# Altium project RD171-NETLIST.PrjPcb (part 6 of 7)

## Sheet 7.SchDoc
size 420 x 297 mm
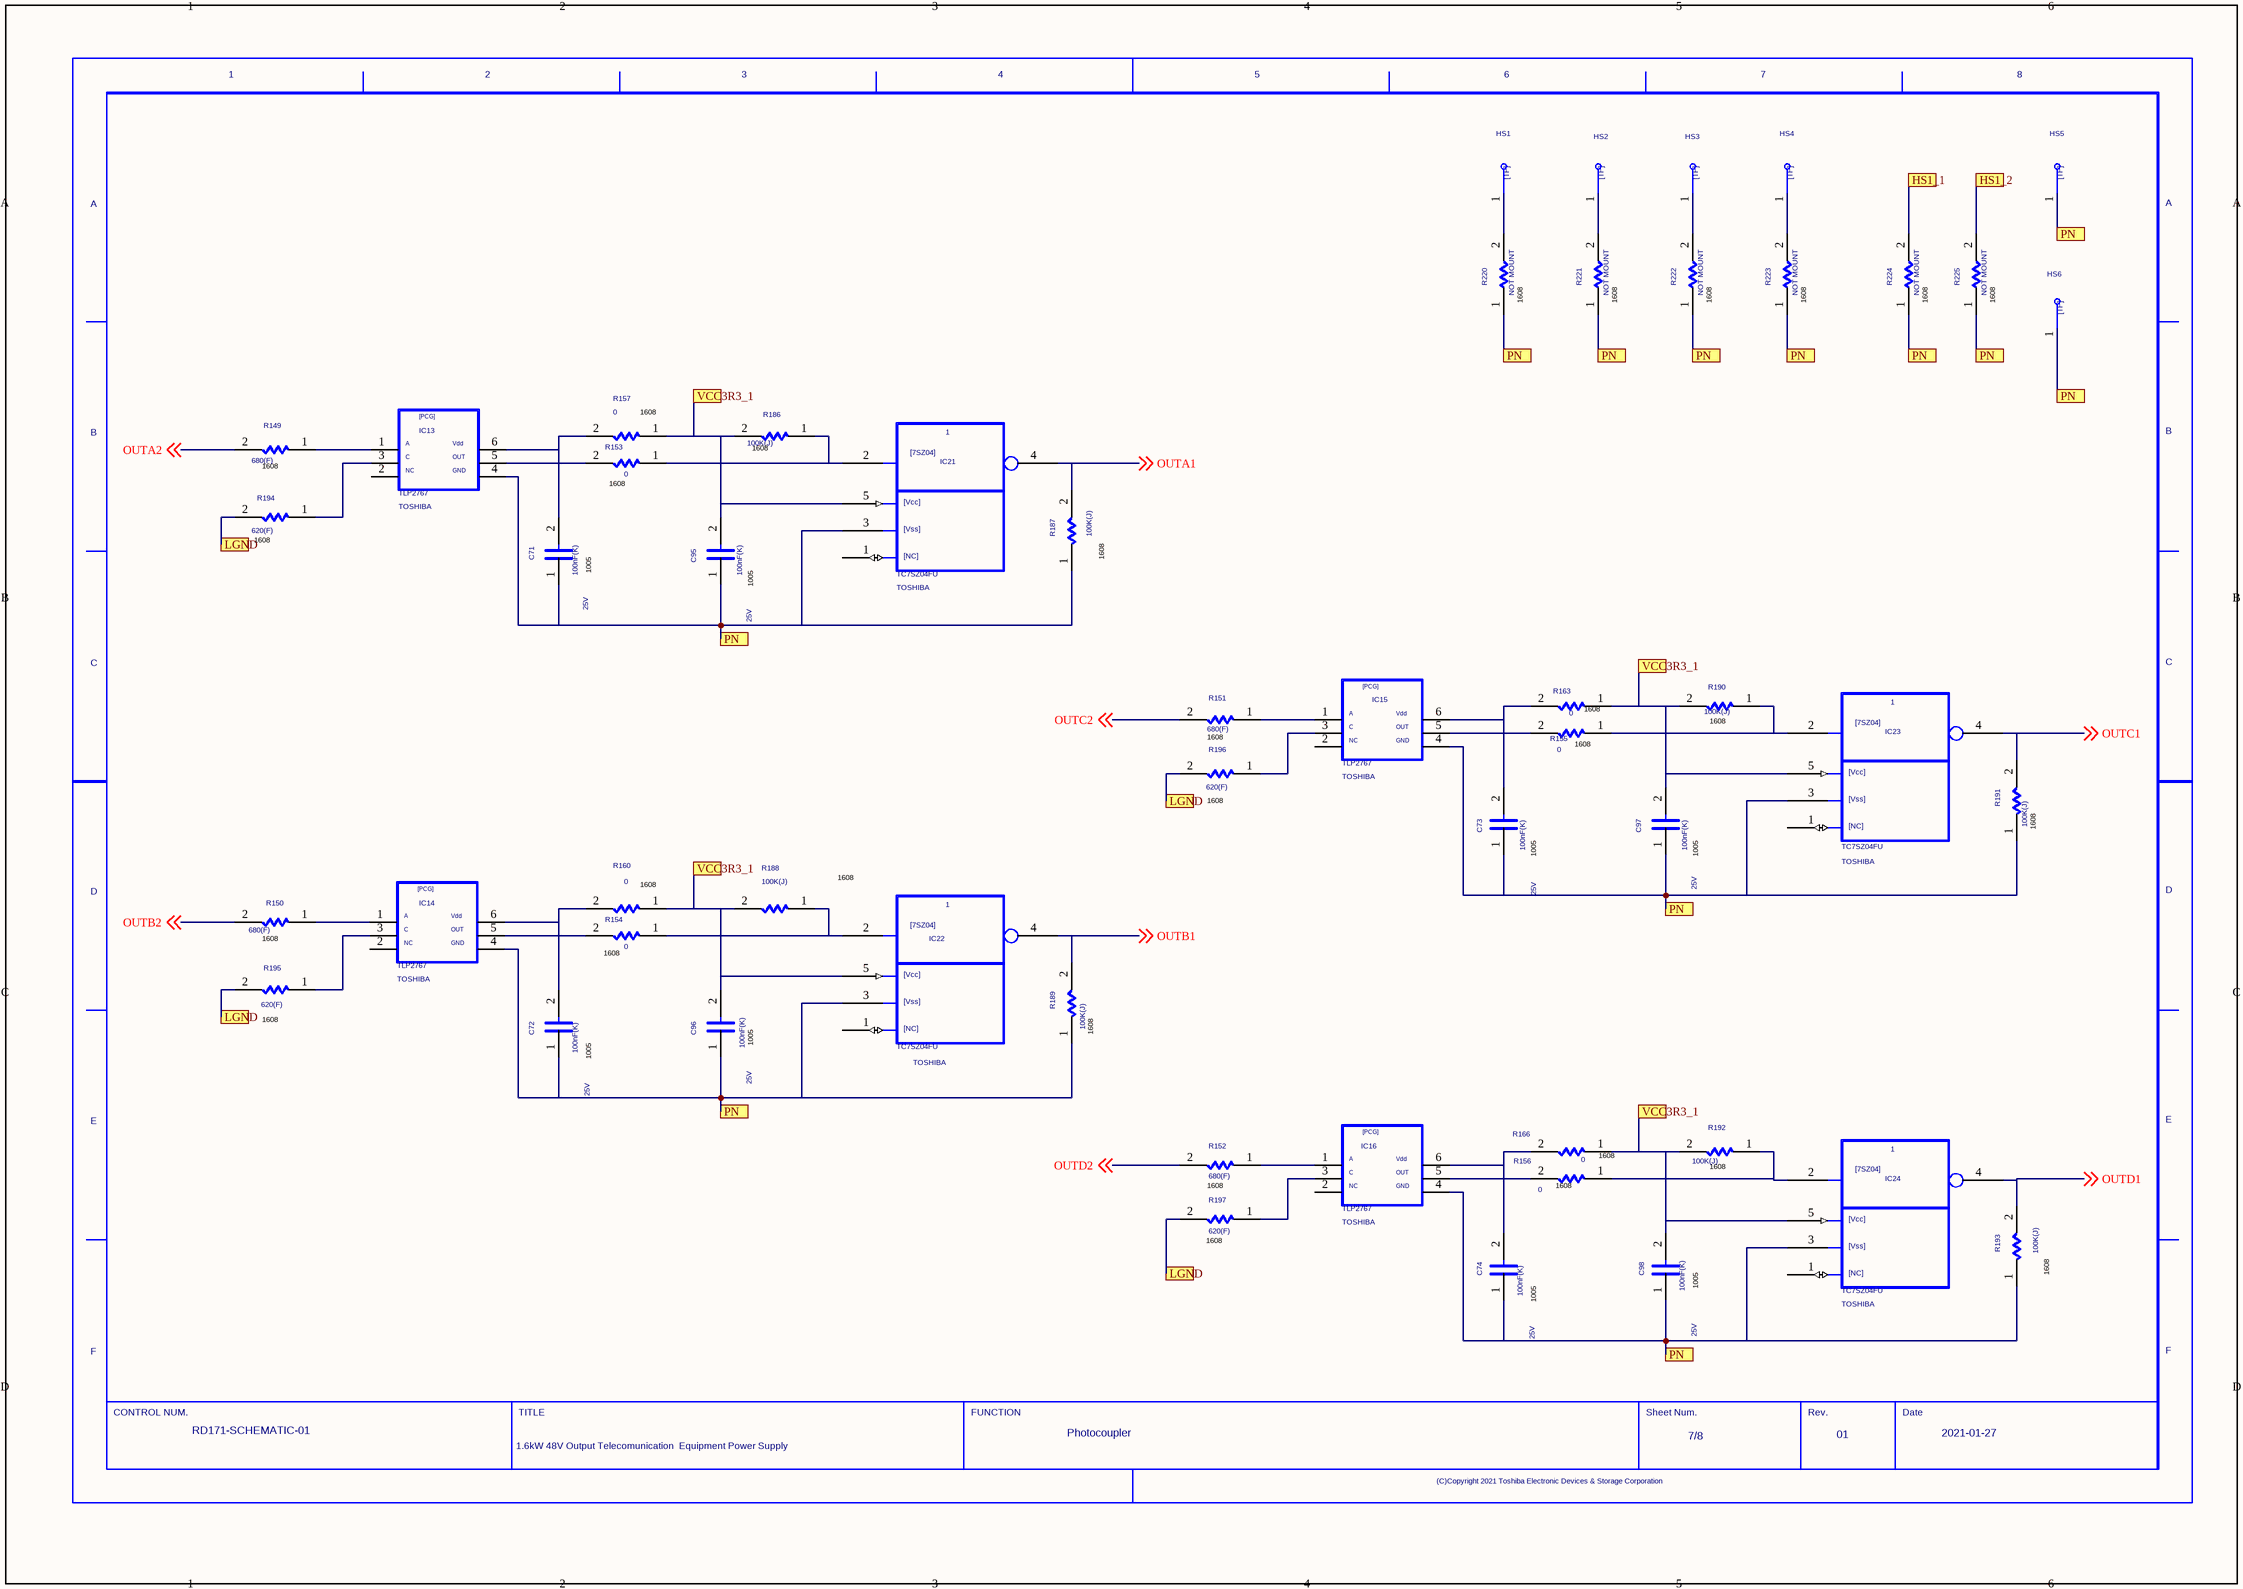
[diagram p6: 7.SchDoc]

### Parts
(Parts that share a designator on the sheet are numbered #1, #2 ... from top to bottom, then left to right.)
C71  VAL2: 25V  VAL1: 100nF(K)  (hidden comment: 100nF)
C72  VAL2: 25V  VAL1: 100nF(K)  (hidden comment: 100nF)
C73  VAL2: 25V  VAL1: 100nF(K)  (hidden comment: 100nF)
C74  VAL2: 25V  VAL1: 100nF(K)  (hidden comment: 100nF)
C95  VAL2: 25V  VAL1: 100nF(K)  (hidden comment: 100nF)
C96  VAL2: 25V  VAL1: 100nF(K)  (hidden comment: 100nF)
C97  VAL2: 25V  VAL1: 100nF(K)  (hidden comment: 100nF)
C98  VAL2: 25V  VAL1: 100nF(K)  (hidden comment: 100nF)
HS1  HS1  [HOLE2.8]  (value not drawn)
HS2  HS2  [HOLE2.8]  (value not drawn)
HS3  HS3  [HOLE2.8]  (value not drawn)
HS4  HS4  [HOLE2.8]  (value not drawn)
HS5  HS5  [HOLE2.0]  (value not drawn)
HS6  HS5  [HOLE2.0]  (value not drawn)
IC13  USERCOMPTEXT3: TOSHIBA  [TLP2767]  (hidden comment: IC13)
IC14  USERCOMPTEXT3: TOSHIBA  [TLP2767]  (hidden comment: IC14)
IC15  USERCOMPTEXT3: TOSHIBA  [TLP2767]  (hidden comment: IC15)
IC16  USERCOMPTEXT3: TOSHIBA  [TLP2767]  (hidden comment: IC16)
IC21  USERCOMPTEXT3: TOSHIBA  [TC7SZ04FU]  (hidden comment: IC21)
IC22  USERCOMPTEXT3: TOSHIBA  [TC7SZ04FU]  (hidden comment: IC22)
IC23  USERCOMPTEXT3: TOSHIBA  [TC7SZ04FU]  (hidden comment: IC23)
IC24  USERCOMPTEXT3: TOSHIBA  [TC7SZ04FU]  (hidden comment: IC24)
R149  VAL1: 680(F)  (hidden comment: 680)
R150  VAL1: 680(F)  (hidden comment: 680)
R151  VAL1: 680(F)  (hidden comment: 680)
R152  VAL1: 680(F)  (hidden comment: 680)
R153  0
R154  0
R155  0
R156  0
R157  0
R160  0
R163  0
R166  0
R186  VAL1: 100K(J)  (hidden comment: 100k)
R187  VAL1: 100K(J)  (hidden comment: 100k)
R188  VAL1: 100K(J)  (hidden comment: 100k)
R189  VAL1: 100K(J)  (hidden comment: 100k)
R190  VAL1: 100K(J)  (hidden comment: 100k)
R191  VAL1: 100K(J)  (hidden comment: 100k)
R192  VAL1: 100K(J)  (hidden comment: 100k)
R193  VAL1: 100K(J)  (hidden comment: 100k)
R194  VAL1: 620(F)  (hidden comment: 620)
R195  VAL1: 620(F)  (hidden comment: 620)
R196  VAL1: 620(F)  (hidden comment: 620)
R197  VAL1: 620(F)  (hidden comment: 620)
R220  NOTMOUNT: NOT MOUNT  (hidden comment: 0)
R221  NOTMOUNT: NOT MOUNT  (hidden comment: 0)
R222  NOTMOUNT: NOT MOUNT  (hidden comment: 0)
R223  NOTMOUNT: NOT MOUNT  (hidden comment: 0)
R224  NOTMOUNT: NOT MOUNT  (hidden comment: 0)
R225  NOTMOUNT: NOT MOUNT  (hidden comment: 0)
U?#7  DATE: 2021-01-27  REVISION: 01  SHEETNUMBER: 7/8  FUNCTION: Photocoupler  TITLE: 1.6kW 48V Output Telecomunication / Equipment Power Supply  DRAWINGNUMBER: RD171-SCHEMATIC-01  (hidden comment: WAKU_DEF100)

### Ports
HS1_1, HS1_2, LGND, PN, VCC3R3_1

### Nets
LGND: R194.2 R195.2 R196.2 R197.2 ; port LGND
OUTA1: IC21.4 R187.2 ; off-sheet OUTA1
OUTA2: R149.2 ; off-sheet OUTA2
OUTB1: IC22.4 R189.2 ; off-sheet OUTB1
OUTB2: R150.2 ; off-sheet OUTB2
OUTC1: IC23.4 R191.2 ; off-sheet OUTC1
OUTC2: R151.2 ; off-sheet OUTC2
OUTD1: IC24.4 R193.2 ; off-sheet OUTD1
OUTD2: R152.2 ; off-sheet OUTD2
SIG228: IC13.5 R153.2
SIG229: C71.2 IC13.6 R157.2
SIG230: IC13.1 R149.1
SIG231: C72.2 IC14.6 R160.2
SIG234: IC14.5 R154.2
SIG236: IC14.1 R150.1
SIG237: C73.2 IC15.6 R163.2
SIG242: IC15.5 R155.2
SIG243: IC16.1 R152.1
SIG245: IC16.5 R156.2
SIG246: C74.2 IC16.6 R166.2
SIG247: IC15.1 R151.1
SIGN284: IC13.3 R194.1
SIGN287: IC14.3 R195.1
SIGN289: IC16.3 R197.1
SIGN291: IC15.3 R196.1
SIGN304: IC21.2 R153.1 R186.1
SIGN305: IC22.2 R154.1 R188.1
SIGN314: IC23.2 R155.1 R190.1
SIGN315: IC24.2 R156.1 R192.1
SIGN366: HS1.1 R220.2
SIGN369: HS2.1 R221.2
SIGN371: HS3.1 R222.2
SIGN373: HS4.1 R223.2
NetC1_1: C71.1 C72.1 C73.1 C74.1 C95.1 C96.1 C97.1 C98.1 HS5.1 HS6.1 IC13.4 IC14.4 IC15.4 IC16.4 IC21.3 IC22.3 IC23.3 IC24.3 R187.1 R189.1 R191.1 R193.1 R220.1 R221.1 R222.1 R223.1 R224.1 R225.1 ; port PN
NetC95_2: C95.2 C96.2 C97.2 C98.2 IC21.5 IC22.5 IC23.5 IC24.5 R157.1 R160.1 R163.1 R166.1 R186.2 R188.2 R190.2 R192.2 ; port VCC3R3_1
NetR224_2: R224.2 ; port HS1_1
NetR225_2: R225.2 ; port HS1_2

Not connected (* = marked no-connect by the designer): IC13 2; IC14 2; IC15 2; IC16 2; IC21 1; IC22 1; IC23 1; IC24 1

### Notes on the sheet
- (near R220) 1608
- (near R221) 1608
- (near R222) 1608
- (near R223) 1608
- (near R224) 1608
- (near R225) 1608
- (near R157) 1608
- (near R186) 1608
- (near R149) 1608
- (near R153) 1608
- (near R194) 1608
- (near C71) 1005
- (near C95) 1005
- (near R187) 1608
- (near R163) 1608
- (near R190) 1608
- (near R196) 1608
- (near R151) 1608
- (near R155) 1608
- (near C73) 1005
- (near C97) 1005
- (near R191) 1608
- (near R160) 1608
- 1608
- (near R150) 1608
- (near R154) 1608
- (near R195) 1608
- (near C72) 1005
- (near C96) 1005
- (near R189) 1608
- (near R156) 1608
- (near R192) 1608
- (near R197) 1608
- (near R193) 1608
- (near C74) 1005
- (near C98) 1005

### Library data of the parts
C71 = C: PARTNAME: Chip1005_GS_2; ORIGINALSYMBOLORIGIN: (0,0); TIME: 16:40:04; UPDATEUSER: t5459927; SAVECOUNT: 1; QUADMODEL: CON_100N; FUNCTION: C_C.Normal_package; NOMINALCAPACITA: 100n; RATEDVOLTAGE: 25; CDMASTERCADCELG: KC0005; MAKER: TDK; SIZECODESMD: 1005; OUMEMAKER: MRT 村田製作所; ADSCNVFLAG: ON; ADSCOMPONENTNAME: C_1005; COMP: PRT_52; ADSMODELNAME: s_GRM155R71E104KE14D; FNLEADFREETHET1GT2GMCTH1: N_N_N; VAL3: C1005X7R1E104K050BB; CAPACITANCETOLE: K; OUMECLASSIFICATION: セラミックコンデンサ; OUMEMAKERKATAMEI: GRM155R71E104KE14D; INSTANCENAME: INS10182
C72 = C: PARTNAME: Chip1005_GS_2; ORIGINALSYMBOLORIGIN: (0,0); TIME: 16:40:04; UPDATEUSER: t5459927; SAVECOUNT: 1; QUADMODEL: CON_100N; FUNCTION: C_C.Normal_package; NOMINALCAPACITA: 100n; RATEDVOLTAGE: 25; CDMASTERCADCELG: KC0005; MAKER: TDK; SIZECODESMD: 1005; OUMEMAKER: MRT 村田製作所; ADSCNVFLAG: ON; ADSCOMPONENTNAME: C_1005; COMP: PRT_52; ADSMODELNAME: s_GRM155R71E104KE14D; FNLEADFREETHET1GT2GMCTH1: N_N_N; VAL3: C1005X7R1E104K050BB; CAPACITANCETOLE: K; OUMECLASSIFICATION: セラミックコンデンサ; OUMEMAKERKATAMEI: GRM155R71E104KE14D; INSTANCENAME: INS10192
C73 = C: PARTNAME: Chip1005_GS_2; ORIGINALSYMBOLORIGIN: (0,0); TIME: 16:40:04; UPDATEUSER: t5459927; SAVECOUNT: 1; QUADMODEL: CON_100N; FUNCTION: C_C.Normal_package; NOMINALCAPACITA: 100n; RATEDVOLTAGE: 25; CDMASTERCADCELG: KC0005; MAKER: TDK; SIZECODESMD: 1005; OUMEMAKER: MRT 村田製作所; ADSCNVFLAG: ON; ADSCOMPONENTNAME: C_1005; COMP: PRT_52; ADSMODELNAME: s_GRM155R71E104KE14D; FNLEADFREETHET1GT2GMCTH1: N_N_N; VAL3: C1005X7R1E104K050BB; CAPACITANCETOLE: K; OUMECLASSIFICATION: セラミックコンデンサ; OUMEMAKERKATAMEI: GRM155R71E104KE14D; INSTANCENAME: INS10222
C74 = C: PARTNAME: Chip1005_GS_2; ORIGINALSYMBOLORIGIN: (0,0); TIME: 16:40:04; UPDATEUSER: t5459927; SAVECOUNT: 1; QUADMODEL: CON_100N; FUNCTION: C_C.Normal_package; NOMINALCAPACITA: 100n; RATEDVOLTAGE: 25; CDMASTERCADCELG: KC0005; MAKER: TDK; SIZECODESMD: 1005; OUMEMAKER: MRT 村田製作所; ADSCNVFLAG: ON; ADSCOMPONENTNAME: C_1005; COMP: PRT_52; ADSMODELNAME: s_GRM155R71E104KE14D; FNLEADFREETHET1GT2GMCTH1: N_N_N; VAL3: C1005X7R1E104K050BB; CAPACITANCETOLE: K; OUMECLASSIFICATION: セラミックコンデンサ; OUMEMAKERKATAMEI: GRM155R71E104KE14D; INSTANCENAME: INS10252
C95 = C: PARTNAME: Chip1005_GS_2; ORIGINALSYMBOLORIGIN: (0,0); TIME: 16:40:04; UPDATEUSER: t5459927; SAVECOUNT: 1; COMPONENTNAME: C_C.Normal_package; SIZECODESMD: 1005; RATEDVOLTAGE: 25; ADSMODELNAME: s_GRM155R71E104KE14D; CAPACITANCETOLE: K; NOMINALCAPACITA: 100n; VAL3: C1005X7R1E104K050BB; MAKER: TDK; COMP: PRT_52; ADSCOMPONENTNAME: C_1005; INSTANCENAME: INS10380
C96 = C: PARTNAME: Chip1005_GS_2; ORIGINALSYMBOLORIGIN: (0,0); TIME: 16:40:04; UPDATEUSER: t5459927; SAVECOUNT: 1; COMPONENTNAME: C_C.Normal_package; SIZECODESMD: 1005; RATEDVOLTAGE: 25; ADSMODELNAME: s_GRM155R71E104KE14D; CAPACITANCETOLE: K; NOMINALCAPACITA: 100n; VAL3: C1005X7R1E104K050BB; MAKER: TDK; COMP: PRT_52; ADSCOMPONENTNAME: C_1005; INSTANCENAME: INS10448
C97 = C: PARTNAME: Chip1005_GS_2; ORIGINALSYMBOLORIGIN: (0,0); TIME: 16:40:04; UPDATEUSER: t5459927; SAVECOUNT: 1; COMPONENTNAME: C_C.Normal_package; SIZECODESMD: 1005; RATEDVOLTAGE: 25; ADSMODELNAME: s_GRM155R71E104KE14D; CAPACITANCETOLE: K; NOMINALCAPACITA: 100n; VAL3: C1005X7R1E104K050BB; MAKER: TDK; COMP: PRT_52; ADSCOMPONENTNAME: C_1005; INSTANCENAME: INS10544
C98 = C: PARTNAME: Chip1005_GS_2; ORIGINALSYMBOLORIGIN: (0,0); TIME: 16:40:04; UPDATEUSER: t5459927; SAVECOUNT: 1; COMPONENTNAME: C_C.Normal_package; SIZECODESMD: 1005; RATEDVOLTAGE: 25; ADSMODELNAME: s_GRM155R71E104KE14D; CAPACITANCETOLE: K; NOMINALCAPACITA: 100n; VAL3: C1005X7R1E104K050BB; MAKER: TDK; COMP: PRT_52; ADSCOMPONENTNAME: C_1005; INSTANCENAME: INS10534
HS1 = TP: PARTNAME: TP_I_TH2.8_TBLC3.8_ILC0_RC3.9_GS; UPDATEUSER: t5459927; UPDATETIME: 16:40:05; SAVECOUNT: 1; SAVEAREA0: -242,-92,12810,7836; ORIGINALSYMBOLORIGIN: (0,0); COMPONENTNAME: TP_TP.Normal_package; COMP: PRT_39; CHIPSIZE: Through Hole; INSTANCENAME: INS10726
HS2 = TP: PARTNAME: TP_I_TH2.8_TBLC3.8_ILC0_RC3.9_GS; UPDATEUSER: t5459927; UPDATETIME: 16:40:05; SAVECOUNT: 1; SAVEAREA0: -242,-92,12810,7836; ORIGINALSYMBOLORIGIN: (0,0); COMPONENTNAME: TP_TP.Normal_package; COMP: PRT_39; CHIPSIZE: Through Hole; INSTANCENAME: INS10734
HS3 = TP: PARTNAME: TP_I_TH2.8_TBLC3.8_ILC0_RC3.9_GS; UPDATEUSER: t5459927; UPDATETIME: 16:40:05; SAVECOUNT: 1; SAVEAREA0: -242,-92,12810,7836; ORIGINALSYMBOLORIGIN: (0,0); COMPONENTNAME: TP_TP.Normal_package; COMP: PRT_39; CHIPSIZE: Through Hole; INSTANCENAME: INS10742
HS4 = TP: PARTNAME: TP_I_TH2.8_TBLC3.8_ILC0_RC3.9_GS; UPDATEUSER: t5459927; UPDATETIME: 16:40:05; SAVECOUNT: 1; SAVEAREA0: -242,-92,12810,7836; ORIGINALSYMBOLORIGIN: (0,0); COMPONENTNAME: TP_TP.Normal_package; COMP: PRT_39; CHIPSIZE: Through Hole; INSTANCENAME: INS10750
HS5 = TP: PARTNAME: BPUS15-25_GS; UPDATEUSER: t5459927; UPDATETIME: 16:40:05; SAVECOUNT: 1; SAVEAREA0: -242,-92,12810,7836; ORIGINALSYMBOLORIGIN: (0,0); COMPONENTNAME: TP_TP.Normal_package; VAL3: BPUS15-25; COMP: PRT_39; CHIPSIZE: Through Hole; INSTANCENAME: INS17030042
HS6 = TP: PARTNAME: BPUS15-25_GS; UPDATEUSER: t5459927; UPDATETIME: 16:40:05; SAVECOUNT: 1; SAVEAREA0: -242,-92,12810,7836; ORIGINALSYMBOLORIGIN: (0,0); COMPONENTNAME: TP_TP.Normal_package; VAL3: BPUS15-25; COMP: PRT_39; CHIPSIZE: Through Hole; INSTANCENAME: INS17030123
IC13 = PCG6PIN: PARTNAME: TLP2767_TS; UPDATEUSER: t5459927; UPDATETIME: 16:40:04; SAVECOUNT: 1; SAVEAREA0: -4197,-437,28946,21425; ORIGINALSYMBOLORIGIN: (0,0); COMPONENTNAME: PCG6PIN_PCG6PIN.Normal_package; COMP: PRT_15; INSTANCENAME: INS10674
IC14 = PCG6PIN: PARTNAME: TLP2767_TS; UPDATEUSER: t5459927; UPDATETIME: 16:40:04; SAVECOUNT: 1; SAVEAREA0: -4197,-437,28946,21425; ORIGINALSYMBOLORIGIN: (0,0); COMPONENTNAME: PCG6PIN_PCG6PIN.Normal_package; COMP: PRT_15; INSTANCENAME: INS10614
IC15 = PCG6PIN: PARTNAME: TLP2767_TS; UPDATEUSER: t5459927; UPDATETIME: 16:40:04; SAVECOUNT: 1; SAVEAREA0: -4197,-437,28946,21425; ORIGINALSYMBOLORIGIN: (0,0); COMPONENTNAME: PCG6PIN_PCG6PIN.Normal_package; COMP: PRT_15; INSTANCENAME: INS10634
IC16 = PCG6PIN: PARTNAME: TLP2767_TS; UPDATEUSER: t5459927; UPDATETIME: 16:40:04; SAVECOUNT: 1; SAVEAREA0: -4197,-437,28946,21425; ORIGINALSYMBOLORIGIN: (0,0); COMPONENTNAME: PCG6PIN_PCG6PIN.Normal_package; COMP: PRT_15; INSTANCENAME: INS10654
IC21 = 7SZ04: PARTNAME: TC7SZ04FU_TS_1; UPDATEUSER: t5459927; UPDATETIME: 16:40:05; SAVECOUNT: 1; SAVEAREA0: -20564,-28567,44956,1635; ORIGINALSYMBOLORIGIN: (0,0); COMPONENTNAME: 7SZ04_7SZ04.Normal_package; COMP: PRT_2; INSTANCENAME: INS10362
IC22 = 7SZ04: PARTNAME: TC7SZ04FU_TS_1; UPDATEUSER: t5459927; UPDATETIME: 16:40:05; SAVECOUNT: 1; SAVEAREA0: -20564,-28567,44956,1635; ORIGINALSYMBOLORIGIN: (0,0); COMPONENTNAME: 7SZ04_7SZ04.Normal_package; COMP: PRT_2; INSTANCENAME: INS10420
IC23 = 7SZ04: PARTNAME: TC7SZ04FU_TS_1; UPDATEUSER: t5459927; UPDATETIME: 16:40:05; SAVECOUNT: 1; SAVEAREA0: -20564,-28567,44956,1635; ORIGINALSYMBOLORIGIN: (0,0); COMPONENTNAME: 7SZ04_7SZ04.Normal_package; COMP: PRT_2; INSTANCENAME: INS10468
IC24 = 7SZ04: PARTNAME: TC7SZ04FU_TS_1; UPDATEUSER: t5459927; UPDATETIME: 16:40:05; SAVECOUNT: 1; SAVEAREA0: -20564,-28567,44956,1635; ORIGINALSYMBOLORIGIN: (0,0); COMPONENTNAME: 7SZ04_7SZ04.Normal_package; COMP: PRT_2; INSTANCENAME: INS10516
R149 = R: PARTNAME: Chip1608_GS_1; ORIGINALSYMBOLORIGIN: (0,0); TIME: 16:40:04; UPDATEUSER: t5459927; SAVECOUNT: 1; COMP: PRT_8; CHIPSIZE: 1608; FUNCTION: R_R.Normal_package; VAL3: RK73H1JTTD6800F; VAL2: 100mW; MAKER: KOA; INSTANCENAME: INS10282
R150 = R: PARTNAME: Chip1608_GS_1; ORIGINALSYMBOLORIGIN: (0,0); TIME: 16:40:04; UPDATEUSER: t5459927; SAVECOUNT: 1; COMP: PRT_8; CHIPSIZE: 1608; FUNCTION: R_R.Normal_package; VAL3: RK73H1JTTD6800F; VAL2: 100mW; MAKER: KOA; INSTANCENAME: INS10292
R151 = R: PARTNAME: Chip1608_GS_1; ORIGINALSYMBOLORIGIN: (0,0); TIME: 16:40:04; UPDATEUSER: t5459927; SAVECOUNT: 1; COMP: PRT_8; CHIPSIZE: 1608; FUNCTION: R_R.Normal_package; VAL3: RK73H1JTTD6800F; VAL2: 100mW; MAKER: KOA; INSTANCENAME: INS10302
R152 = R: PARTNAME: Chip1608_GS_1; ORIGINALSYMBOLORIGIN: (0,0); TIME: 16:40:04; UPDATEUSER: t5459927; SAVECOUNT: 1; COMP: PRT_8; CHIPSIZE: 1608; FUNCTION: R_R.Normal_package; VAL3: RK73H1JTTD6800F; VAL2: 100mW; MAKER: KOA; INSTANCENAME: INS10312
R153 = R: PARTNAME: Chip1608_GS_1; ORIGINALSYMBOLORIGIN: (0,0); TIME: 16:40:04; UPDATEUSER: t5459927; SAVECOUNT: 1; QUADMODEL: RES_0; FUNCTION: R_R.Normal_package; CDMASTERCADCELG: KC0005; MAKER: KOA; RESISTANCETOLER: X; SIZECODESMD: 1005; OUMEMAKER: NAE パナソニックエレクトロニックデバイス; ADSCNVFLAG: ON; POWERRATING: 63m; MOUNTINGFORMSMD: SMD; ADSCOMPONENTNAME: R_1005; COMP: PRT_8; ADSMODELNAME: s_ERJ2GE0R00X; PMPRODUCTSTYPEG: HD1-PC1; FNLEADFREETHET1GT2GMCTH1: 2_1_N; VAL3: RK73Z1JTTD; VAL2: 100mW; OUMECLASSIFICATION: 表面実装用固定抵抗器; OUMEMAKERKATAMEI: ERJ2GE0R00X; CHIPSIZE: 1608; INSTANCENAME: INS10162
R154 = R: PARTNAME: Chip1608_GS_1; ORIGINALSYMBOLORIGIN: (0,0); TIME: 16:40:04; UPDATEUSER: t5459927; SAVECOUNT: 1; QUADMODEL: RES_0; FUNCTION: R_R.Normal_package; CDMASTERCADCELG: KC0005; MAKER: KOA; RESISTANCETOLER: X; SIZECODESMD: 1005; OUMEMAKER: NAE パナソニックエレクトロニックデバイス; ADSCNVFLAG: ON; POWERRATING: 63m; MOUNTINGFORMSMD: SMD; ADSCOMPONENTNAME: R_1005; COMP: PRT_8; ADSMODELNAME: s_ERJ2GE0R00X; PMPRODUCTSTYPEG: HD1-PC1; FNLEADFREETHET1GT2GMCTH1: 2_1_N; VAL3: RK73Z1JTTD; VAL2: 100mW; OUMECLASSIFICATION: 表面実装用固定抵抗器; OUMEMAKERKATAMEI: ERJ2GE0R00X; CHIPSIZE: 1608; INSTANCENAME: INS10212
R155 = R: PARTNAME: Chip1608_GS_1; ORIGINALSYMBOLORIGIN: (0,0); TIME: 16:40:04; UPDATEUSER: t5459927; SAVECOUNT: 1; QUADMODEL: RES_0; FUNCTION: R_R.Normal_package; CDMASTERCADCELG: KC0005; MAKER: KOA; RESISTANCETOLER: X; SIZECODESMD: 1005; OUMEMAKER: NAE パナソニックエレクトロニックデバイス; ADSCNVFLAG: ON; POWERRATING: 63m; MOUNTINGFORMSMD: SMD; ADSCOMPONENTNAME: R_1005; COMP: PRT_8; ADSMODELNAME: s_ERJ2GE0R00X; PMPRODUCTSTYPEG: HD1-PC1; FNLEADFREETHET1GT2GMCTH1: 2_1_N; VAL3: RK73Z1JTTD; VAL2: 100mW; OUMECLASSIFICATION: 表面実装用固定抵抗器; OUMEMAKERKATAMEI: ERJ2GE0R00X; CHIPSIZE: 1608; INSTANCENAME: INS10262
R156 = R: PARTNAME: Chip1608_GS_1; ORIGINALSYMBOLORIGIN: (0,0); TIME: 16:40:04; UPDATEUSER: t5459927; SAVECOUNT: 1; QUADMODEL: RES_0; FUNCTION: R_R.Normal_package; CDMASTERCADCELG: KC0005; MAKER: KOA; RESISTANCETOLER: X; SIZECODESMD: 1005; OUMEMAKER: NAE パナソニックエレクトロニックデバイス; ADSCNVFLAG: ON; POWERRATING: 63m; MOUNTINGFORMSMD: SMD; ADSCOMPONENTNAME: R_1005; COMP: PRT_8; ADSMODELNAME: s_ERJ2GE0R00X; PMPRODUCTSTYPEG: HD1-PC1; FNLEADFREETHET1GT2GMCTH1: 2_1_N; VAL3: RK73Z1JTTD; VAL2: 100mW; OUMECLASSIFICATION: 表面実装用固定抵抗器; OUMEMAKERKATAMEI: ERJ2GE0R00X; CHIPSIZE: 1608; INSTANCENAME: INS10242
R157 = R: PARTNAME: Chip1608_GS_1; ORIGINALSYMBOLORIGIN: (0,0); TIME: 16:40:04; UPDATEUSER: t5459927; SAVECOUNT: 1; QUADMODEL: RES_0; FUNCTION: R_R.Normal_package; CDMASTERCADCELG: KC0005; MAKER: KOA; RESISTANCETOLER: X; SIZECODESMD: 1005; OUMEMAKER: NAE パナソニックエレクトロニックデバイス; ADSCNVFLAG: ON; POWERRATING: 63m; MOUNTINGFORMSMD: SMD; ADSCOMPONENTNAME: R_1005; COMP: PRT_8; ADSMODELNAME: s_ERJ2GE0R00X; PMPRODUCTSTYPEG: HD1-PC1; FNLEADFREETHET1GT2GMCTH1: 2_1_N; VAL3: RK73Z1JTTD; VAL2: 100mW; OUMECLASSIFICATION: 表面実装用固定抵抗器; OUMEMAKERKATAMEI: ERJ2GE0R00X; CHIPSIZE: 1608; INSTANCENAME: INS10172
R160 = R: PARTNAME: Chip1608_GS_1; ORIGINALSYMBOLORIGIN: (0,0); TIME: 16:40:04; UPDATEUSER: t5459927; SAVECOUNT: 1; QUADMODEL: RES_0; FUNCTION: R_R.Normal_package; CDMASTERCADCELG: KC0005; MAKER: KOA; RESISTANCETOLER: X; SIZECODESMD: 1005; OUMEMAKER: NAE パナソニックエレクトロニックデバイス; ADSCNVFLAG: ON; POWERRATING: 63m; MOUNTINGFORMSMD: SMD; ADSCOMPONENTNAME: R_1005; COMP: PRT_8; ADSMODELNAME: s_ERJ2GE0R00X; PMPRODUCTSTYPEG: HD1-PC1; FNLEADFREETHET1GT2GMCTH1: 2_1_N; VAL3: RK73Z1JTTD; VAL2: 100mW; OUMECLASSIFICATION: 表面実装用固定抵抗器; OUMEMAKERKATAMEI: ERJ2GE0R00X; CHIPSIZE: 1608; INSTANCENAME: INS10202
R163 = R: PARTNAME: Chip1608_GS_1; ORIGINALSYMBOLORIGIN: (0,0); TIME: 16:40:04; UPDATEUSER: t5459927; SAVECOUNT: 1; QUADMODEL: RES_0; FUNCTION: R_R.Normal_package; CDMASTERCADCELG: KC0005; MAKER: KOA; RESISTANCETOLER: X; SIZECODESMD: 1005; OUMEMAKER: NAE パナソニックエレクトロニックデバイス; ADSCNVFLAG: ON; POWERRATING: 63m; MOUNTINGFORMSMD: SMD; ADSCOMPONENTNAME: R_1005; COMP: PRT_8; ADSMODELNAME: s_ERJ2GE0R00X; PMPRODUCTSTYPEG: HD1-PC1; FNLEADFREETHET1GT2GMCTH1: 2_1_N; VAL3: RK73Z1JTTD; VAL2: 100mW; OUMECLASSIFICATION: 表面実装用固定抵抗器; OUMEMAKERKATAMEI: ERJ2GE0R00X; CHIPSIZE: 1608; INSTANCENAME: INS10232
R166 = R: PARTNAME: Chip1608_GS_1; ORIGINALSYMBOLORIGIN: (0,0); TIME: 16:40:04; UPDATEUSER: t5459927; SAVECOUNT: 1; QUADMODEL: RES_0; FUNCTION: R_R.Normal_package; CDMASTERCADCELG: KC0005; MAKER: KOA; RESISTANCETOLER: X; SIZECODESMD: 1005; OUMEMAKER: NAE パナソニックエレクトロニックデバイス; ADSCNVFLAG: ON; POWERRATING: 63m; MOUNTINGFORMSMD: SMD; ADSCOMPONENTNAME: R_1005; COMP: PRT_8; ADSMODELNAME: s_ERJ2GE0R00X; PMPRODUCTSTYPEG: HD1-PC1; FNLEADFREETHET1GT2GMCTH1: 2_1_N; VAL3: RK73Z1JTTD; VAL2: 100mW; OUMECLASSIFICATION: 表面実装用固定抵抗器; OUMEMAKERKATAMEI: ERJ2GE0R00X; CHIPSIZE: 1608; INSTANCENAME: INS10272
R186 = R: PARTNAME: Chip1608_GS_1; ORIGINALSYMBOLORIGIN: (0,0); TIME: 16:40:04; UPDATEUSER: t5459927; SAVECOUNT: 1; COMP: PRT_8; CHIPSIZE: 1608; FUNCTION: R_R.Normal_package; VAL3: RK73B1JTTD104J; VAL2: 100mW,±5%; MAKER: KOA; INSTANCENAME: INS10390
R187 = R: PARTNAME: Chip1608_GS_1; ORIGINALSYMBOLORIGIN: (0,0); TIME: 16:40:04; UPDATEUSER: t5459927; SAVECOUNT: 1; COMP: PRT_8; CHIPSIZE: 1608; FUNCTION: R_R.Normal_package; VAL3: RK73B1JTTD104J; VAL2: 100mW,±5%; MAKER: KOA; INSTANCENAME: INS10400
R188 = R: PARTNAME: Chip1608_GS_1; ORIGINALSYMBOLORIGIN: (0,0); TIME: 16:40:04; UPDATEUSER: t5459927; SAVECOUNT: 1; COMP: PRT_8; CHIPSIZE: 1608; FUNCTION: R_R.Normal_package; VAL3: RK73B1JTTD104J; VAL2: 100mW,±5%; MAKER: KOA; INSTANCENAME: INS10410
R189 = R: PARTNAME: Chip1608_GS_1; ORIGINALSYMBOLORIGIN: (0,0); TIME: 16:40:04; UPDATEUSER: t5459927; SAVECOUNT: 1; COMP: PRT_8; CHIPSIZE: 1608; FUNCTION: R_R.Normal_package; VAL3: RK73B1JTTD104J; VAL2: 100mW,±5%; MAKER: KOA; INSTANCENAME: INS10438
R190 = R: PARTNAME: Chip1608_GS_1; ORIGINALSYMBOLORIGIN: (0,0); TIME: 16:40:04; UPDATEUSER: t5459927; SAVECOUNT: 1; COMP: PRT_8; CHIPSIZE: 1608; FUNCTION: R_R.Normal_package; VAL3: RK73B1JTTD104J; VAL2: 100mW,±5%; MAKER: KOA; INSTANCENAME: INS10458
R191 = R: PARTNAME: Chip1608_GS_1; ORIGINALSYMBOLORIGIN: (0,0); TIME: 16:40:04; UPDATEUSER: t5459927; SAVECOUNT: 1; COMP: PRT_8; CHIPSIZE: 1608; FUNCTION: R_R.Normal_package; VAL3: RK73B1JTTD104J; VAL2: 100mW,±5%; MAKER: KOA; INSTANCENAME: INS10486
R192 = R: PARTNAME: Chip1608_GS_1; ORIGINALSYMBOLORIGIN: (0,0); TIME: 16:40:04; UPDATEUSER: t5459927; SAVECOUNT: 1; COMP: PRT_8; CHIPSIZE: 1608; FUNCTION: R_R.Normal_package; VAL3: RK73B1JTTD104J; VAL2: 100mW,±5%; MAKER: KOA; INSTANCENAME: INS10506
R193 = R: PARTNAME: Chip1608_GS_1; ORIGINALSYMBOLORIGIN: (0,0); TIME: 16:40:04; UPDATEUSER: t5459927; SAVECOUNT: 1; COMP: PRT_8; CHIPSIZE: 1608; FUNCTION: R_R.Normal_package; VAL3: RK73B1JTTD104J; VAL2: 100mW,±5%; MAKER: KOA; INSTANCENAME: INS10496
R194 = R: PARTNAME: Chip1608_GS_1; ORIGINALSYMBOLORIGIN: (0,0); TIME: 16:40:04; UPDATEUSER: t5459927; SAVECOUNT: 1; COMP: PRT_8; CHIPSIZE: 1608; FUNCTION: R_R.Normal_package; VAL3: ERJ-3EKF6200V; VAL2: 100mW; MAKER: PANASONIC; INSTANCENAME: INS10322
R195 = R: PARTNAME: Chip1608_GS_1; ORIGINALSYMBOLORIGIN: (0,0); TIME: 16:40:04; UPDATEUSER: t5459927; SAVECOUNT: 1; COMP: PRT_8; CHIPSIZE: 1608; FUNCTION: R_R.Normal_package; VAL3: ERJ-3EKF6200V; VAL2: 100mW; MAKER: PANASONIC; INSTANCENAME: INS10332
R196 = R: PARTNAME: Chip1608_GS_1; ORIGINALSYMBOLORIGIN: (0,0); TIME: 16:40:04; UPDATEUSER: t5459927; SAVECOUNT: 1; COMP: PRT_8; CHIPSIZE: 1608; FUNCTION: R_R.Normal_package; VAL3: ERJ-3EKF6200V; VAL2: 100mW; MAKER: PANASONIC; INSTANCENAME: INS10352
R197 = R: PARTNAME: Chip1608_GS_1; ORIGINALSYMBOLORIGIN: (0,0); TIME: 16:40:04; UPDATEUSER: t5459927; SAVECOUNT: 1; COMP: PRT_8; CHIPSIZE: 1608; FUNCTION: R_R.Normal_package; VAL3: ERJ-3EKF6200V; VAL2: 100mW; MAKER: PANASONIC; INSTANCENAME: INS10342
R220 = R: PARTNAME: Chip1608_GS_1; ORIGINALSYMBOLORIGIN: (0,0); TIME: 16:40:04; UPDATEUSER: t5459927; SAVECOUNT: 1; QUADMODEL: RES_0; FUNCTION: R_R.Normal_package; CDMASTERCADCELG: KC0005; MAKER: KOA; RESISTANCETOLER: X; SIZECODESMD: 1005; OUMEMAKER: HDK 北陸電気工業; ADSCNVFLAG: ON; POWERRATING: 63m; MOUNTINGFORMSMD: SMD; ADSCOMPONENTNAME: R_1005; COMP: PRT_8; ADSMODELNAME: s_CR10_000V; FNLEADFREETHET1GT2GMCTH1: N_N_N; VAL3: RK73Z1JTTD; VAL2: 100mW; OUMECLASSIFICATION: 表面実装用固定抵抗器; OUMEMAKERKATAMEI: CR10-000V; CHIPSIZE: 1608; INSTANCENAME: INS10554
R221 = R: PARTNAME: Chip1608_GS_1; ORIGINALSYMBOLORIGIN: (0,0); TIME: 16:40:04; UPDATEUSER: t5459927; SAVECOUNT: 1; QUADMODEL: RES_0; FUNCTION: R_R.Normal_package; CDMASTERCADCELG: KC0005; MAKER: KOA; RESISTANCETOLER: X; SIZECODESMD: 1005; OUMEMAKER: HDK 北陸電気工業; ADSCNVFLAG: ON; POWERRATING: 63m; MOUNTINGFORMSMD: SMD; ADSCOMPONENTNAME: R_1005; COMP: PRT_8; ADSMODELNAME: s_CR10_000V; FNLEADFREETHET1GT2GMCTH1: N_N_N; VAL3: RK73Z1JTTD; VAL2: 100mW; OUMECLASSIFICATION: 表面実装用固定抵抗器; OUMEMAKERKATAMEI: CR10-000V; CHIPSIZE: 1608; INSTANCENAME: INS10564
R222 = R: PARTNAME: Chip1608_GS_1; ORIGINALSYMBOLORIGIN: (0,0); TIME: 16:40:04; UPDATEUSER: t5459927; SAVECOUNT: 1; QUADMODEL: RES_0; FUNCTION: R_R.Normal_package; CDMASTERCADCELG: KC0005; MAKER: KOA; RESISTANCETOLER: X; SIZECODESMD: 1005; OUMEMAKER: HDK 北陸電気工業; ADSCNVFLAG: ON; POWERRATING: 63m; MOUNTINGFORMSMD: SMD; ADSCOMPONENTNAME: R_1005; COMP: PRT_8; ADSMODELNAME: s_CR10_000V; FNLEADFREETHET1GT2GMCTH1: N_N_N; VAL3: RK73Z1JTTD; VAL2: 100mW; OUMECLASSIFICATION: 表面実装用固定抵抗器; OUMEMAKERKATAMEI: CR10-000V; CHIPSIZE: 1608; INSTANCENAME: INS10574
R223 = R: PARTNAME: Chip1608_GS_1; ORIGINALSYMBOLORIGIN: (0,0); TIME: 16:40:04; UPDATEUSER: t5459927; SAVECOUNT: 1; QUADMODEL: RES_0; FUNCTION: R_R.Normal_package; CDMASTERCADCELG: KC0005; MAKER: KOA; RESISTANCETOLER: X; SIZECODESMD: 1005; OUMEMAKER: HDK 北陸電気工業; ADSCNVFLAG: ON; POWERRATING: 63m; MOUNTINGFORMSMD: SMD; ADSCOMPONENTNAME: R_1005; COMP: PRT_8; ADSMODELNAME: s_CR10_000V; FNLEADFREETHET1GT2GMCTH1: N_N_N; VAL3: RK73Z1JTTD; VAL2: 100mW; OUMECLASSIFICATION: 表面実装用固定抵抗器; OUMEMAKERKATAMEI: CR10-000V; CHIPSIZE: 1608; INSTANCENAME: INS10584
R224 = R: PARTNAME: Chip1608_GS_1; ORIGINALSYMBOLORIGIN: (0,0); TIME: 16:40:04; UPDATEUSER: t5459927; SAVECOUNT: 1; QUADMODEL: RES_0; FUNCTION: R_R.Normal_package; CDMASTERCADCELG: KC0005; MAKER: KOA; RESISTANCETOLER: X; SIZECODESMD: 1005; OUMEMAKER: HDK 北陸電気工業; ADSCNVFLAG: ON; POWERRATING: 63m; MOUNTINGFORMSMD: SMD; ADSCOMPONENTNAME: R_1005; COMP: PRT_8; ADSMODELNAME: s_CR10_000V; FNLEADFREETHET1GT2GMCTH1: N_N_N; VAL3: RK73Z1JTTD; VAL2: 100mW; OUMECLASSIFICATION: 表面実装用固定抵抗器; OUMEMAKERKATAMEI: CR10-000V; CHIPSIZE: 1608; INSTANCENAME: INS10594
R225 = R: PARTNAME: Chip1608_GS_1; ORIGINALSYMBOLORIGIN: (0,0); TIME: 16:40:04; UPDATEUSER: t5459927; SAVECOUNT: 1; QUADMODEL: RES_0; FUNCTION: R_R.Normal_package; CDMASTERCADCELG: KC0005; MAKER: KOA; RESISTANCETOLER: X; SIZECODESMD: 1005; OUMEMAKER: HDK 北陸電気工業; ADSCNVFLAG: ON; POWERRATING: 63m; MOUNTINGFORMSMD: SMD; ADSCOMPONENTNAME: R_1005; COMP: PRT_8; ADSMODELNAME: s_CR10_000V; FNLEADFREETHET1GT2GMCTH1: N_N_N; VAL3: RK73Z1JTTD; VAL2: 100mW; OUMECLASSIFICATION: 表面実装用固定抵抗器; OUMEMAKERKATAMEI: CR10-000V; CHIPSIZE: 1608; INSTANCENAME: INS10604
U?#7 = WAKU_DEF100: PLOTTIME: HH:MM; SAVEAREA0: 168739,-66042,466246,90057; TIME: 14:30:25; UPDATEUSER: t5459927; UPDATETIME: 15:16:58; SAVECOUNT: 5; OriginalSymbolOrigin: (10160,284480)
